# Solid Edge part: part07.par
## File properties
Author: CADCIM
Template: Normal.par
Last saved by: Ashutosh-CADCIM
Revision: 6
Application: Solid Edge
Accuracy: 0.99
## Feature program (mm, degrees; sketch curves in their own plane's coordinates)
sketch for "unnamed Protrusion 1" #1 plane through (0, 0, 0) normal (0, 0, 1) x-axis (1, 0, 0)
  circle centre (17.5, 12.5) radius 2.5
sketch for "unnamed Protrusion 1" #2 plane through (0, 0, 0) normal (0, 0, 1) x-axis (1, 0, 0)
  circle centre (17.5, -12.5) radius 2.5
sketch for "unnamed Protrusion 1" #3 plane through (0, 0, 0) normal (0, 0, 1) x-axis (1, 0, 0)
  line (-17.5, 2.5) -> (-22.5, 2.5)
  line (-22.5, 2.5) -> (-22.5, 5.5)
  arc centre (-20.5, 5.5) radius 2 from (-22.5, 5.5) to (-20.5, 7.5) cw
  line (-20.5, 7.5) -> (10.5, 7.5)
  arc centre (10.5, 9.5) radius 2 from (10.5, 7.5) to (12.5, 9.5) ccw
  line (12.5, 9.5) -> (12.5, 12.5)
  arc centre (17.5, 12.5) radius 5 from (12.5, 12.5) to (22.5, 12.5) cw
  line (22.5, 12.5) -> (22.5, -12.5)
  arc centre (17.5, -12.5) radius 5 from (12.5, -12.5) to (22.5, -12.5) ccw
  line (12.5, -9.5) -> (12.5, -12.5)
  arc centre (10.5, -9.5) radius 2 from (10.5, -7.5) to (12.5, -9.5) cw
  line (-20.5, -7.5) -> (10.5, -7.5)
  arc centre (-20.5, -5.5) radius 2 from (-22.5, -5.5) to (-20.5, -7.5) ccw
  line (-22.5, -2.5) -> (-22.5, -5.5)
  line (-17.5, -2.5) -> (-22.5, -2.5)
  arc centre (-17.5, 0) radius 2.5 from (-17.5, 2.5) to (-17.5, -2.5) cw
  dimension (linear) = 22.5
  dimension (linear) = 17.5
extrude "unnamed Protrusion 1" add finite 5 along +normal
sketch for "ExtrudedProtrusion_2" #1 plane through (6.5901, 0, 20.9099) normal (0.707107, 0, 0.707107) x-axis (0, 1, 0)
  circle centre (0, -5.5) radius 3.75
sketch for "ExtrudedProtrusion_2" #2 plane through (6.5901, 0, 20.9099) normal (0.707107, 0, 0.707107) x-axis (0, 1, 0)
  line (-7.5, -22.5) -> (-7.5, -5.5)
  arc centre (0, -5.5) radius 7.5 from (7.5, -5.5) to (-7.5, -5.5) ccw
  line (7.5, -5.5) -> (7.5, -22.5)
  line (7.5, -22.5) -> (-7.5, -22.5)
  dimension (linear) = 7.5
extrude "ExtrudedProtrusion_2" add through along -normal
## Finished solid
Body 1: solid body, 26 faces, 64 edges, 38 vertices.
  Faces by surface: plane 15, cylinder 11
  Edges by curve: line 42, circle 20, ellipse 2
Bounding box of the edges (mm): 45.000 x 35.000 x 22.324, from (-22.5, -17.5, 0) to (22.5, 17.5, 22.3241).
Cylindrical faces by radius (mm): R2 x4, R2.5 x3, R3.75 x1, R5 x2, R7.5 x1
Planar faces by outward normal: +x 1, +y 2, +z 4, -x 4, -y 2, -z 1, oblique 1
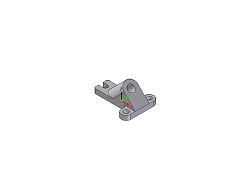
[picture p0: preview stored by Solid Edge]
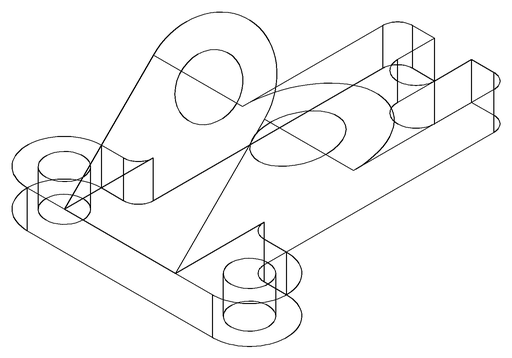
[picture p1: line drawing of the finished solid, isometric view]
